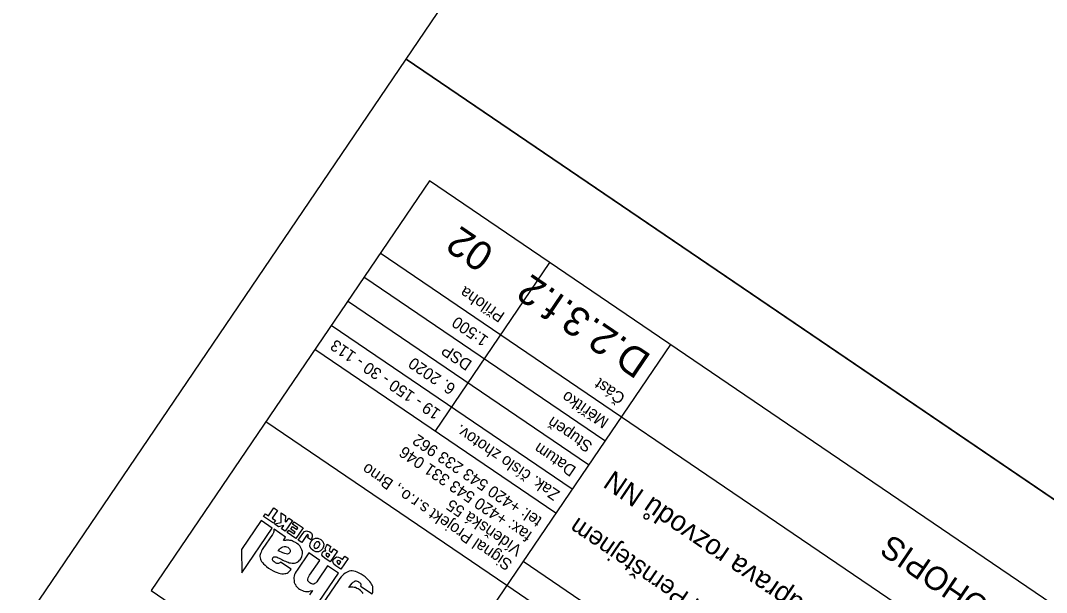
# Model space of a CAD drawing. Extents: x -620624 to -619936, y -1122925 to -1122325.
# Drawn here: x -620573.5 to -620485.4, y -1122493.6 to -1122444.5 of the extents above; entities that cross this region are included whole.
import ezdxf

# ---------------------------------------------------------------- set-up
doc = ezdxf.new("R2010")
doc.units = 0
for name, color, linetype in [('060601_EOV', 7, 'Continuous'), ('060602_NAPÁJENÍ_NN', 7, 'Continuous'), ('060603_ROZVODY_NN', 7, 'Continuous'), ('060604_ROZVODY_SEE', 7, 'Continuous'), ('POPIS KABELOVÉ TRASY', 7, 'Continuous'), ('UZEMNĚNÍ', 7, 'Continuous')]:
    doc.layers.add(name, color=color, linetype=linetype)

msp = doc.modelspace()

# ---------------------------------------------------------------- linework, layer by layer
at = {"layer": '060601_EOV'}
for points in [[(-620456.955, -1122325.018), (-620370.093, -1122384.009), (-620453.523, -1122506.857), (-620540.385, -1122447.866)], [(-620540.385, -1122447.866), (-620019.213, -1122801.814), (-620102.643, -1122924.661), (-620623.816, -1122570.714)]]:
    msp.add_lwpolyline(points, close=True, dxfattribs=at)
at = {"layer": '060603_ROZVODY_NN'}
for points in [[(-620551.779, -1122487.67), (-620552.628, -1122487.094), (-620552.466, -1122486.854), (-620552.195, -1122487.038), (-620551.734, -1122486.359), (-620551.433, -1122486.563), (-620551.894, -1122487.242), (-620551.617, -1122487.431), (-620551.779, -1122487.67)], [(-620550.768, -1122488.357), (-620551.077, -1122488.147), (-620550.878, -1122487.854), (-620551.339, -1122487.969), (-620551.694, -1122487.728), (-620551.119, -1122487.611), (-620551.109, -1122486.783), (-620550.747, -1122487.029), (-620550.769, -1122487.544), (-620550.652, -1122487.522), (-620550.453, -1122487.229), (-620550.145, -1122487.438), (-620550.768, -1122488.357)], [(-620549.85, -1122488.98), (-620550.599, -1122488.472), (-620550.457, -1122488.264), (-620550.009, -1122488.568), (-620549.915, -1122488.428), (-620550.293, -1122488.172), (-620550.146, -1122487.956), (-620549.768, -1122488.213), (-620549.674, -1122488.073), (-620550.145, -1122487.754), (-620549.998, -1122487.538), (-620549.226, -1122488.062), (-620549.85, -1122488.98)], [(-620549.356, -1122489.316), (-620549.657, -1122489.111), (-620549.269, -1122488.54), (-620549.118, -1122488.384), (-620548.949, -1122488.318), (-620548.663, -1122488.411), (-620548.519, -1122488.531), (-620548.445, -1122488.671), (-620548.447, -1122488.84), (-620548.526, -1122489.023), (-620548.58, -1122489.087), (-620548.851, -1122488.903), (-620548.761, -1122488.738), (-620548.792, -1122488.65), (-620548.867, -1122488.644), (-620548.942, -1122488.706), (-620549.356, -1122489.316)], [(-620548.377, -1122490.015), (-620548.564, -1122489.842), (-620548.653, -1122489.624), (-620548.633, -1122489.412), (-620548.543, -1122489.214), (-620548.381, -1122489.042), (-620548.184, -1122488.951), (-620547.956, -1122488.947), (-620547.722, -1122489.05), (-620547.532, -1122489.235), (-620547.448, -1122489.461), (-620547.476, -1122489.668), (-620547.571, -1122489.874), (-620547.727, -1122490.038), (-620547.92, -1122490.122), (-620548.147, -1122490.125), (-620548.377, -1122490.015)], [(-620548.225, -1122489.791), (-620548.137, -1122489.828), (-620548.052, -1122489.818), (-620547.874, -1122489.657), (-620547.784, -1122489.425), (-620547.874, -1122489.274), (-620548.073, -1122489.251), (-620548.227, -1122489.395), (-620548.311, -1122489.619), (-620548.299, -1122489.718), (-620548.225, -1122489.791)], [(-620546.91, -1122490.977), (-620547.358, -1122490.673), (-620547.548, -1122490.521), (-620547.637, -1122490.37), (-620547.581, -1122490.138), (-620547.435, -1122490.023), (-620547.275, -1122490.019), (-620547.343, -1122489.837), (-620547.261, -1122489.667), (-620547.214, -1122489.598), (-620547.174, -1122489.523), (-620547.182, -1122489.484), (-620547.166, -1122489.461), (-620546.857, -1122489.671), (-620546.952, -1122489.843), (-620546.998, -1122490.026), (-620546.941, -1122490.076), (-620546.854, -1122490.147), (-620546.808, -1122490.178), (-620546.587, -1122489.854), (-620546.286, -1122490.058), (-620546.91, -1122490.977)], [(-620547.07, -1122490.564), (-620546.944, -1122490.379), (-620547.075, -1122490.29), (-620547.204, -1122490.247), (-620547.264, -1122490.285), (-620547.28, -1122490.376), (-620547.216, -1122490.464), (-620547.07, -1122490.564)], [(-620545.984, -1122491.606), (-620546.424, -1122491.307), (-620546.583, -1122491.176), (-620546.665, -1122491.031), (-620546.674, -1122490.878), (-620546.597, -1122490.716), (-620546.373, -1122490.552), (-620546.203, -1122490.566), (-620546.01, -1122490.664), (-620545.855, -1122490.768), (-620545.661, -1122490.483), (-620545.36, -1122490.687), (-620545.984, -1122491.606)], [(-620546.144, -1122491.193), (-620546.002, -1122490.985), (-620546.133, -1122490.896), (-620546.226, -1122490.866), (-620546.322, -1122490.925), (-620546.339, -1122491.015), (-620546.228, -1122491.135), (-620546.144, -1122491.193)]]:
    msp.add_lwpolyline(points, dxfattribs=at)
at = {"layer": 'POPIS KABELOVÉ TRASY'}
for p, q in [((-620538.395, -1122458.284), (-620562.272, -1122493.442)), ((-620463.941, -1122508.848), (-620538.395, -1122458.284)), ((-620468.155, -1122515.052), (-620542.608, -1122464.488)), ((-620523.331, -1122480.602), (-620544.013, -1122466.556)), ((-620524.736, -1122482.67), (-620545.417, -1122468.625)), ((-620526.14, -1122484.738), (-620546.822, -1122470.693)), ((-620527.545, -1122486.806), (-620548.226, -1122472.761)), ((-620517.713, -1122472.329), (-620541.591, -1122507.488)), ((-620476.582, -1122527.461), (-620530.354, -1122490.943)), ((-620477.987, -1122529.529), (-620531.759, -1122493.011)), ((-620562.272, -1122493.442), (-620487.819, -1122544.006))]:
    msp.add_line(p, q, dxfattribs=at)
for points in [[(-620537.886, -1122479.784), (-620528.054, -1122465.307)], [(-620531.759, -1122493.011), (-620552.44, -1122478.965)]]:
    msp.add_lwpolyline(points, dxfattribs=at)
at = {"layer": 'UZEMNĚNÍ'}
for points in [[(-620554.486, -1122491.921), (-620551.881, -1122488.086), (-620552.838, -1122487.436), (-620554.531, -1122489.928), (-620554.486, -1122491.921)], [(-620550.266, -1122491.618), (-620551.184, -1122490.995), (-620551.239, -1122491.059), (-620551.291, -1122491.102), (-620551.348, -1122491.12), (-620551.408, -1122491.125), (-620551.475, -1122491.124), (-620551.547, -1122491.098), (-620551.601, -1122491.061), (-620551.663, -1122491.019), (-620551.732, -1122490.972), (-620551.797, -1122490.917), (-620551.83, -1122490.849), (-620551.85, -1122490.813), (-620551.86, -1122490.761), (-620551.87, -1122490.709), (-620551.844, -1122490.671), (-620551.833, -1122490.621), (-620551.791, -1122490.593), (-620551.752, -1122490.552), (-620551.692, -1122490.548), (-620551.633, -1122490.543), (-620551.558, -1122490.549), (-620551.47, -1122490.586), (-620551.375, -1122490.628), (-620551.28, -1122490.671), (-620551.182, -1122490.726), (-620551.071, -1122490.778), (-620550.968, -1122490.826), (-620550.857, -1122490.878), (-620550.741, -1122490.923), (-620550.63, -1122490.976), (-620550.525, -1122491.003), (-620550.421, -1122491.05), (-620550.303, -1122491.075), (-620550.179, -1122491.091), (-620550.059, -1122491.082), (-620549.964, -1122491.09), (-620549.868, -1122491.065), (-620549.788, -1122491.03), (-620549.731, -1122491.012), (-620549.66, -1122490.958), (-620549.603, -1122490.907), (-620549.54, -1122490.848), (-620549.491, -1122490.792), (-620549.443, -1122490.722), (-620549.33, -1122490.506), (-620549.282, -1122490.302), (-620549.288, -1122490.095), (-620549.338, -1122489.937), (-620549.417, -1122489.77), (-620549.527, -1122489.617), (-620549.637, -1122489.497), (-620549.771, -1122489.395), (-620549.832, -1122489.353), (-620549.892, -1122489.324), (-620549.953, -1122489.282), (-620550.033, -1122489.25), (-620550.085, -1122489.227), (-620550.16, -1122489.187), (-620550.232, -1122489.161), (-620550.296, -1122489.14), (-620550.371, -1122489.134), (-620550.446, -1122489.128), (-620550.516, -1122489.114), (-620550.604, -1122489.111), (-620550.677, -1122489.118), (-620550.754, -1122489.133), (-620550.848, -1122489.137), (-620550.92, -1122489.144), (-620550.742, -1122488.848), (-620551.729, -1122488.178), (-620551.755, -1122488.216), (-620551.738, -1122488.307), (-620551.741, -1122488.361), (-620551.744, -1122488.415), (-620551.765, -1122488.446), (-620551.781, -1122488.503), (-620551.802, -1122488.534), (-620551.833, -1122488.58), (-620551.875, -1122488.642), (-620552.683, -1122489.831), (-620552.751, -1122489.931), (-620552.796, -1122490.047), (-620552.843, -1122490.15), (-620552.891, -1122490.253), (-620552.92, -1122490.346), (-620552.939, -1122490.423), (-620552.947, -1122490.519), (-620552.925, -1122490.636), (-620552.892, -1122490.737), (-620552.854, -1122490.83), (-620552.793, -1122490.939), (-620552.719, -1122491.046), (-620552.627, -1122491.143), (-620552.498, -1122491.253), (-620552.362, -1122491.367), (-620552.208, -1122491.506), (-620552.01, -1122491.629), (-620551.799, -1122491.75), (-620551.636, -1122491.826), (-620551.474, -1122491.903), (-620551.317, -1122491.953), (-620551.19, -1122491.983), (-620551.053, -1122491.997), (-620550.931, -1122492.001), (-620550.812, -1122491.991), (-620550.717, -1122491.966), (-620550.608, -1122491.939), (-620550.524, -1122491.883), (-620550.467, -1122491.831), (-620550.391, -1122491.77), (-620550.323, -1122491.703), (-620550.266, -1122491.618)], [(-620551.373, -1122490.044), (-620551.367, -1122490.036), (-620551.352, -1122490.013), (-620551.341, -1122489.997), (-620551.252, -1122489.9), (-620551.171, -1122489.797), (-620551.08, -1122489.746), (-620550.971, -1122489.685), (-620550.862, -1122489.657), (-620550.759, -1122489.671), (-620550.648, -1122489.69), (-620550.547, -1122489.725), (-620550.478, -1122489.772), (-620550.442, -1122489.819), (-620550.411, -1122489.873), (-620550.381, -1122489.928), (-620550.356, -1122489.99), (-620550.343, -1122490.055), (-620550.338, -1122490.114), (-620550.373, -1122490.181), (-620550.456, -1122490.271), (-620550.563, -1122490.312), (-620550.687, -1122490.295), (-620550.808, -1122490.258), (-620550.96, -1122490.2), (-620551.086, -1122490.136), (-620551.236, -1122490.091), (-620551.373, -1122490.044)], [(-620547.853, -1122494.374), (-620546.202, -1122491.943), (-620547.128, -1122491.314), (-620547.972, -1122492.556), (-620548.061, -1122492.687), (-620548.168, -1122492.795), (-620548.254, -1122492.839), (-620548.326, -1122492.879), (-620548.406, -1122492.881), (-620548.489, -1122492.87), (-620548.572, -1122492.825), (-620548.659, -1122492.788), (-620548.726, -1122492.721), (-620548.769, -1122492.668), (-620548.823, -1122492.598), (-620548.83, -1122492.525), (-620548.824, -1122492.451), (-620548.808, -1122492.36), (-620548.75, -1122492.242), (-620548.677, -1122492.133), (-620547.807, -1122490.852), (-620548.748, -1122490.213), (-620549.744, -1122491.679), (-620549.833, -1122491.811), (-620549.909, -1122491.939), (-620549.965, -1122492.071), (-620550, -1122492.205), (-620550.024, -1122492.324), (-620550.035, -1122492.44), (-620550.013, -1122492.557), (-620550.014, -1122492.658), (-620549.989, -1122492.754), (-620549.956, -1122492.855), (-620549.894, -1122492.93), (-620549.844, -1122493.022), (-620549.772, -1122493.115), (-620549.705, -1122493.183), (-620549.639, -1122493.251), (-620549.546, -1122493.314), (-620549.43, -1122493.392), (-620549.294, -1122493.44), (-620549.182, -1122493.493), (-620549.038, -1122493.512), (-620548.901, -1122493.526), (-620548.748, -1122493.517), (-620548.595, -1122493.474), (-620548.421, -1122493.435), (-620548.678, -1122493.813)], [(-620544.072, -1122493.705), (-620544.138, -1122493.604), (-620544.223, -1122493.512), (-620544.313, -1122493.429), (-620544.421, -1122493.355), (-620544.514, -1122493.292), (-620544.609, -1122493.25), (-620544.727, -1122493.192), (-620544.846, -1122493.168), (-620544.957, -1122493.149), (-620545.079, -1122493.145), (-620545.177, -1122493.157), (-620545.299, -1122493.187), (-620545.147, -1122492.963), (-620545.037, -1122492.801), (-620544.933, -1122492.714), (-620544.837, -1122492.656), (-620544.764, -1122492.615), (-620544.678, -1122492.605), (-620544.606, -1122492.632), (-620544.521, -1122492.656), (-620544.444, -1122492.708), (-620544.405, -1122492.735), (-620544.356, -1122492.779), (-620544.321, -1122492.826), (-620544.292, -1122492.867), (-620544.29, -1122492.914), (-620544.273, -1122492.971), (-620544.286, -1122493.007), (-620544.297, -1122493.056), (-620543.317, -1122493.722), (-620543.256, -1122493.582), (-620543.245, -1122493.466), (-620543.236, -1122493.337), (-620543.243, -1122493.231), (-620543.255, -1122493.099), (-620543.316, -1122492.989), (-620543.374, -1122492.893), (-620543.433, -1122492.764), (-620543.504, -1122492.67), (-620543.589, -1122492.578), (-620543.666, -1122492.492), (-620543.758, -1122492.396), (-620543.838, -1122492.33), (-620543.91, -1122492.27), (-620543.997, -1122492.2), (-620544.066, -1122492.152), (-620544.242, -1122492.045), (-620544.414, -1122491.95), (-620544.584, -1122491.869), (-620544.728, -1122491.816), (-620544.878, -1122491.77), (-620545.023, -1122491.751), (-620545.15, -1122491.755), (-620545.271, -1122491.785), (-620545.399, -1122491.823), (-620545.516, -1122491.879), (-620545.63, -1122491.948), (-620545.747, -1122492.037), (-620545.846, -1122492.15), (-620545.979, -1122492.263), (-620546.079, -1122492.409), (-620546.194, -1122492.579), (-620547.557, -1122494.586)]]:
    msp.add_lwpolyline(points, dxfattribs=at)

# ---------------------------------------------------------------- texts
at = {"layer": '060602_NAPÁJENÍ_NN'}
for s, p in [('Příloha', (-620531.843, -1122469.684)), ('1:500', (-620533.247, -1122471.752)), ('19 - 150 - 30 - 113', (-620537.346, -1122478.035)), ('DSP', (-620534.652, -1122473.82)), ('6. 2020', (-620536.056, -1122475.889)), ('Část', (-620521.502, -1122476.707)), ('Měřítko', (-620522.907, -1122478.775)), ('Stupeň', (-620524.311, -1122480.843)), ('Zak. číslo zhotov.', (-620527.12, -1122484.98)), ('tel: +420 543 233 962', (-620528.658, -1122487.26)), ('fax: +420 543 331 046', (-620529.5, -1122488.5)), ('Datum', (-620525.716, -1122482.911)), ('Signal Projekt s.r.o., Brno', (-620531.193, -1122490.977)), ('Vídeňská 55', (-620530.35, -1122489.736))]:
    msp.add_text(s, height=1, rotation=145.81812, dxfattribs=at).set_placement(p)
at = {"layer": '060604_ROZVODY_SEE'}
for s, height, p in [('02', 2.5, (-620532.688, -1122464.174)), ('D.2.3.f.2', 2.5, (-620519.243, -1122473.305)), ('SO 06-06-03 Bystřice nad Pernštějnem, úprava rozvodů NN', 1.72959, (-620471.784, -1122517.581)), ('Oprava zabezpečovacího zařízení v ŽST Bystřice nad Pernštejnem', 1.55893, (-620474.315, -1122521.998)), ('POLOHOPIS', 2, (-620485.726, -1122497.409))]:
    msp.add_text(s, height=height, rotation=145.81812, dxfattribs=at).set_placement(p)

doc.saveas('drawing.dxf')
